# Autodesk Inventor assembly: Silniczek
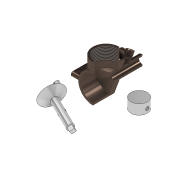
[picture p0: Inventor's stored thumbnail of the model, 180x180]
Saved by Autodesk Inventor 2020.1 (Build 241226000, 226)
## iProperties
Manager: www.cadconsulting.pl
Company: Fabian Stasiak CAD Consulting
Created: 2019-06
Part Number: Silniczek
Document SubType Name: Assembly
Designer: F.Stasiak
Author: F.Stasiak
Subject: Zbiór ćwiczeń. Autodesk Inventor 2020. Kurs podstawowy
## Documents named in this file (4)
- C:\2020_Kurs_podstawowy\R6 Zespoły\Wiązania\Silniczek\Silniczek.iam
- C:\2020_Kurs_podstawowy\R6 Zespoły\Wiązania\Silniczek\Korpus_234.ipt
- C:\2020_Kurs_podstawowy\R6 Zespoły\Wiązania\Silniczek\Wałek_234.ipt
- C:\2020_Kurs_podstawowy\R6 Zespoły\Wiązania\Silniczek\Tłok_234.ipt
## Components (3 placed, 3 different names)
1. Korpus_234:1
2. Wałek_234:1
3. Tłok_234:1
